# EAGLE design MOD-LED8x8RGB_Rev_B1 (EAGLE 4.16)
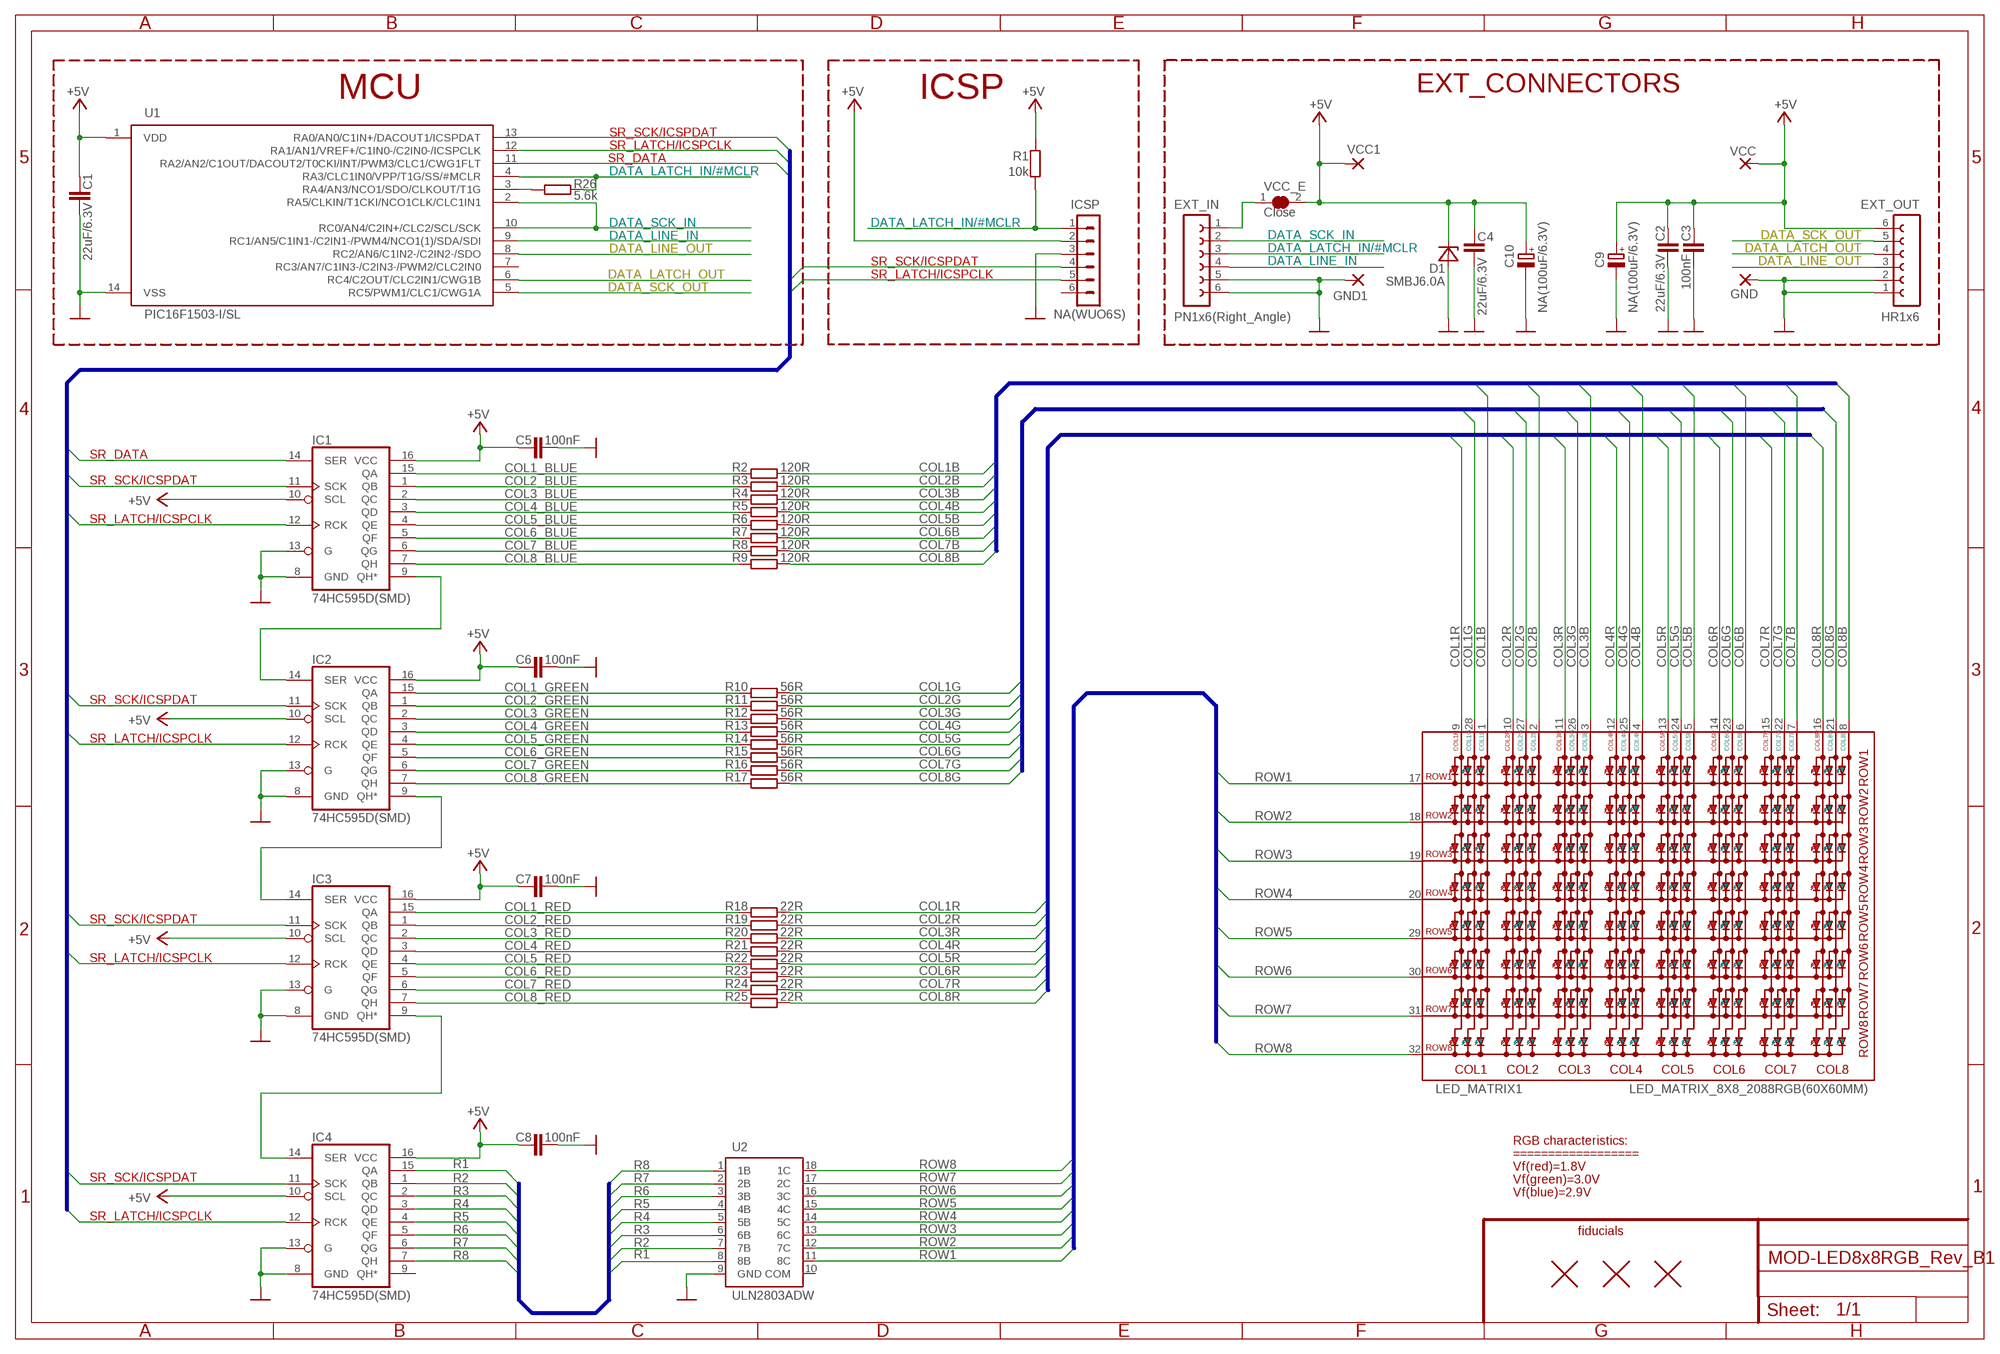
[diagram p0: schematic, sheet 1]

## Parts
C1  22uF/6.3V  C-EUC0603_DWS  [C0603_DWS]
C2  22uF/6.3V  C-EUC0603_DWS  [C0603_DWS]
C3  100nF  C-EUC0603_DWS  [C0603_DWS]
C4  22uF/6.3V  C-EUC0603_DWS  [C0603_DWS]
C5  100nF  C-EUC0603_DWS  [C0603_DWS]
C6  100nF  C-EUC0603_DWS  [C0603_DWS]
C7  100nF  C-EUC0603_DWS  [C0603_DWS]
C8  100nF  C-EUC0603_DWS  [C0603_DWS]
C9  NA(100uF/6.3V)  CPOL-EUC-SMD5X11-M  [C-SMD5X11-M]
C10  NA(100uF/6.3V)  CPOL-EUC-SMD5X11  [C-SMD5X11]
D1  SMBJ6.0A  SMBJ16A  [DO214AA]
EXT_IN  PN1x6(Right_Angle)  FE06W  [FE06W]
EXT_OUT  HR1x6  FE06W  [FE06W]
FID1  FIDUCIAL1X2  [FIDUCIAL-1X2]
FID2  FIDUCIAL1X2  [FIDUCIAL-1X2]
FID3  FIDUCIAL1X2  [FIDUCIAL-1X2]
GND  3,17/1,3  [3,17/1,3]
GND1  3,17/1,3  [3,17/1,3]
IC1  74HC595D(SMD)  74LS595D  [SO16]
IC2  74HC595D(SMD)  74LS595D  [SO16]
IC3  74HC595D(SMD)  74LS595D  [SO16]
IC4  74HC595D(SMD)  74LS595D  [SO16]
ICSP  NA(WUO6S)  CON6WUO6S  [WU06S]
LED_MATRIX1  LED_MATRIX_8X8_2088RGB(60X60MM)  [LED_MATRIX_8X8RGB_60X60MM]
R1  10k  R-EU_R0603_5MIL_DWS  [R0603_5MIL_DWS]
R2  120R  R-EU_R1206_5MIL_WS  [R1206_5MIL_WS]
R3  120R  R-EU_R1206_5MIL_WS  [R1206_5MIL_WS]
R4  120R  R-EU_R1206_5MIL_WS  [R1206_5MIL_WS]
R5  120R  R-EU_R1206_5MIL_WS  [R1206_5MIL_WS]
R6  120R  R-EU_R1206_5MIL_WS  [R1206_5MIL_WS]
R7  120R  R-EU_R1206_5MIL_WS  [R1206_5MIL_WS]
R8  120R  R-EU_R1206_5MIL_WS  [R1206_5MIL_WS]
R9  120R  R-EU_R1206_5MIL_WS  [R1206_5MIL_WS]
R10  56R  R-EU_R1206_5MIL_WS  [R1206_5MIL_WS]
R11  56R  R-EU_R1206_5MIL_WS  [R1206_5MIL_WS]
R12  56R  R-EU_R1206_5MIL_WS  [R1206_5MIL_WS]
R13  56R  R-EU_R1206_5MIL_WS  [R1206_5MIL_WS]
R14  56R  R-EU_R1206_5MIL_WS  [R1206_5MIL_WS]
R15  56R  R-EU_R1206_5MIL_WS  [R1206_5MIL_WS]
R16  56R  R-EU_R1206_5MIL_WS  [R1206_5MIL_WS]
R17  56R  R-EU_R1206_5MIL_WS  [R1206_5MIL_WS]
R18  22R  R-EU_R1206_5MIL_WS  [R1206_5MIL_WS]
R19  22R  R-EU_R1206_5MIL_WS  [R1206_5MIL_WS]
R20  22R  R-EU_R1206_5MIL_WS  [R1206_5MIL_WS]
R21  22R  R-EU_R1206_5MIL_WS  [R1206_5MIL_WS]
R22  22R  R-EU_R1206_5MIL_WS  [R1206_5MIL_WS]
R23  22R  R-EU_R1206_5MIL_WS  [R1206_5MIL_WS]
R24  22R  R-EU_R1206_5MIL_WS  [R1206_5MIL_WS]
R25  22R  R-EU_R1206_5MIL_WS  [R1206_5MIL_WS]
R26  5.6k  R-EU_R0603_5MIL_DWS  [R0603_5MIL_DWS]
U1  PIC16F1503-I/SL  PIC16F1503  [SOIC14]
U2  ULN2803ADW  [SO18-150MILS/2]
VCC  3,17/1,3  [3,17/1,3]
VCC1  3,17/1,3  [3,17/1,3]
VCC_E  Close  SJSJ-CLOSE  [SJ-CLOSE]

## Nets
+5V: C1.1 C2.1 C3.1 C4.1 C5.1 C6.1 C7.1 C8.1 C9.+ C10.+ D1.C EXT_OUT.6 IC1.10(SCL) IC1.16(VCC) IC2.10(SCL) IC2.16(VCC) IC3.10(SCL) IC3.16(VCC) IC4.10(SCL) IC4.16(VCC) ICSP.2 R1.1 U1.1(VDD) VCC1.1(P) VCC.1(P) VCC_E.2
COL1_BLUE: IC1.15(QA) R2.1
COL1_GREEN: IC2.15(QA) R10.1
COL1_RED: IC3.15(QA) R18.1
COL1B: LED_MATRIX1.1(COL1B) R2.2
COL1G: LED_MATRIX1.28(COL1G) R10.2
COL1R: LED_MATRIX1.9(COL1R) R18.2
COL2_BLUE: IC1.1(QB) R3.1
COL2_GREEN: IC2.1(QB) R11.1
COL2_RED: IC3.1(QB) R19.1
COL2B: LED_MATRIX1.2(COL2B) R3.2
COL2G: LED_MATRIX1.27(COL2G) R11.2
COL2R: LED_MATRIX1.10(COL2R) R19.2
COL3_BLUE: IC1.2(QC) R4.1
COL3_GREEN: IC2.2(QC) R12.1
COL3_RED: IC3.2(QC) R20.1
COL3B: LED_MATRIX1.3(COL3B) R4.2
COL3G: LED_MATRIX1.26(COL3G) R12.2
COL3R: LED_MATRIX1.11(COL3R) R20.2
COL4_BLUE: IC1.3(QD) R5.1
COL4_GREEN: IC2.3(QD) R13.1
COL4_RED: IC3.3(QD) R21.1
COL4B: LED_MATRIX1.4(COL4B) R5.2
COL4G: LED_MATRIX1.25(COL4G) R13.2
COL4R: LED_MATRIX1.12(COL4R) R21.2
COL5_BLUE: IC1.4(QE) R6.1
COL5_GREEN: IC2.4(QE) R14.1
COL5_RED: IC3.4(QE) R22.1
COL5B: LED_MATRIX1.5(COL5B) R6.2
COL5G: LED_MATRIX1.24(COL5G) R14.2
COL5R: LED_MATRIX1.13(COL5R) R22.2
COL6_BLUE: IC1.5(QF) R7.1
COL6_GREEN: IC2.5(QF) R15.1
COL6_RED: IC3.5(QF) R23.1
COL6B: LED_MATRIX1.6(COL6B) R7.2
COL6G: LED_MATRIX1.23(COL6G) R15.2
COL6R: LED_MATRIX1.14(COL6R) R23.2
COL7_BLUE: IC1.6(QG) R8.1
COL7_GREEN: IC2.6(QG) R16.1
COL7_RED: IC3.6(QG) R24.1
COL7B: LED_MATRIX1.7(COL7B) R8.2
COL7G: LED_MATRIX1.22(COL7G) R16.2
COL7R: LED_MATRIX1.15(COL7R) R24.2
COL8_BLUE: IC1.7(QH) R9.1
COL8_GREEN: IC2.7(QH) R17.1
COL8_RED: IC3.7(QH) R25.1
COL8B: LED_MATRIX1.8(COL8B) R9.2
COL8G: LED_MATRIX1.21(COL8G) R17.2
COL8R: LED_MATRIX1.16(COL8R) R25.2
DATA_LATCH_IN/#MCLR: EXT_IN.3 ICSP.1 R1.2 R26.2 U1.4(RA3/CLC1IN0/VPP/T1G/SS/#MCLR)
DATA_LATCH_OUT: EXT_OUT.4 U1.6(RC4/C2OUT/CLC2IN1/CWG1B)
DATA_LINE_IN: EXT_IN.4 U1.9(RC1/AN5/C1IN1-/C2IN1-/PWM4/NCO1(1)/SDA/SDI)
DATA_LINE_OUT: EXT_OUT.3 U1.8(RC2/AN6/C1IN2-/C2IN2-/SDO)
DATA_SCK_IN: EXT_IN.2 U1.2(RA5/CLKIN/T1CKI/NCO1CLK/CLC1IN1) U1.10(RC0/AN4/C2IN+/CLC2/SCL/SCK)
DATA_SCK_OUT: EXT_OUT.5 U1.5(RC5/PWM1/CLC1/CWG1A)
GND: C1.2 C2.2 C3.2 C4.2 C5.2 C6.2 C7.2 C8.2 C9.- C10.- D1.A EXT_IN.5 EXT_IN.6 EXT_OUT.1 EXT_OUT.2 GND1.1(P) GND.1(P) IC1.8(GND) IC1.13(G) IC2.8(GND) IC2.13(G) IC3.8(GND) IC3.13(G) IC4.8(GND) IC4.13(G) ICSP.3 U1.14(VSS) U2.9(GND)
N$1: R26.1 U1.3(RA4/AN3/NCO1/SDO/CLKOUT/T1G)
N$15: EXT_IN.1 VCC_E.1
N$29: IC3.9(QH*) IC4.14(SER)
N$45: IC1.9(QH*) IC2.14(SER)
N$46: IC2.9(QH*) IC3.14(SER)
R1: IC4.15(QA) U2.8(8B)
R2: IC4.1(QB) U2.7(7B)
R3: IC4.2(QC) U2.6(6B)
R4: IC4.3(QD) U2.5(5B)
R5: IC4.4(QE) U2.4(4B)
R6: IC4.5(QF) U2.3(3B)
R7: IC4.6(QG) U2.2(2B)
R8: IC4.7(QH) U2.1(1B)
ROW1: LED_MATRIX1.17(ROW1) U2.11(8C)
ROW2: LED_MATRIX1.18(ROW2) U2.12(7C)
ROW3: LED_MATRIX1.19(ROW3) U2.13(6C)
ROW4: LED_MATRIX1.20(ROW4) U2.14(5C)
ROW5: LED_MATRIX1.29(ROW5) U2.15(4C)
ROW6: LED_MATRIX1.30(ROW6) U2.16(3C)
ROW7: LED_MATRIX1.31(ROW7) U2.17(2C)
ROW8: LED_MATRIX1.32(ROW8) U2.18(1C)
SR_DATA: IC1.14(SER) U1.11(RA2/AN2/C1OUT/DACOUT2/T0CKI/INT/PWM3/CLC1/CWG1FLT)
SR_LATCH/ICSPCLK: IC1.12(RCK) IC2.12(RCK) IC3.12(RCK) IC4.12(RCK) ICSP.5 U1.12(RA1/AN1/VREF+/C1IN0-/C2IN0-/ICSPCLK)
SR_SCK/ICSPDAT: IC1.11(SCK) IC2.11(SCK) IC3.11(SCK) IC4.11(SCK) ICSP.4 U1.13(RA0/AN0/C1IN+/DACOUT1/ICSPDAT)
Unconnected: IC4.9(QH*) ICSP.6 U1.7(RC3/AN7/C1IN3-/C2IN3-/PWM2/CLC2IN0) U2.10(COM)

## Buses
SR_SCK,SR_LATCH,SR_DATA
COL1B,COL2B,COL3B,COL4B,COL5B,COL6B,COL7B,COL8B
COL1G,COL2G,COL3G,COL4G,COL5G,COL6G,COL7G,COL8G
COL1R,COL2R,COL3R,COL4R,COL5R,COL6R,COL7R,COL8R
R[1..8]
ROW[1..8]

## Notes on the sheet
- MCU | ICSP | EXT_CONNECTORS
- RGB characteristics:
- ==================
- Vf(red)=1.8V
- Vf(green)=3.0V
- Vf(blue)=2.9V
- fiducials

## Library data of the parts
C1-C8 = rcl:C-EU: CAPACITOR, European symbol
C9 C10 = rcl:CPOL-EU: POLARIZED CAPACITOR, European symbol
D1 = OLIMEX_DISCRET:SMBJ16A
EXT_IN EXT_OUT = con-lsta:FE06W: FEMALE HEADER
FID1-FID3 = SparkFunEagle-6-6-07:FIDUCIAL: Fiducial Alignment Points
GND GND1 VCC VCC1 = wirepad:3,17/1,3: THROUGH-HOLE PAD
IC1-IC4 = SparkFun:74*595: 8-bit SHIFT REGISTER, output latch
ICSP = Penko:CON6: CONNECTORS - 6 PINS
LED_MATRIX1 = OLIMEX_DISCRET:LED_MATRIX_8X8_2088RGB
R1-R26 = rcl:R-EU_: RESISTOR, European symbol
U1 = OLIMEX_IC:PIC16F1503
U2 = OLIMEX_IC:ULN2803
VCC_E = jumper:SJ: SMD solder JUMPER

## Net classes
1 pwr: width 1.016 mm, drill 0.241 mm

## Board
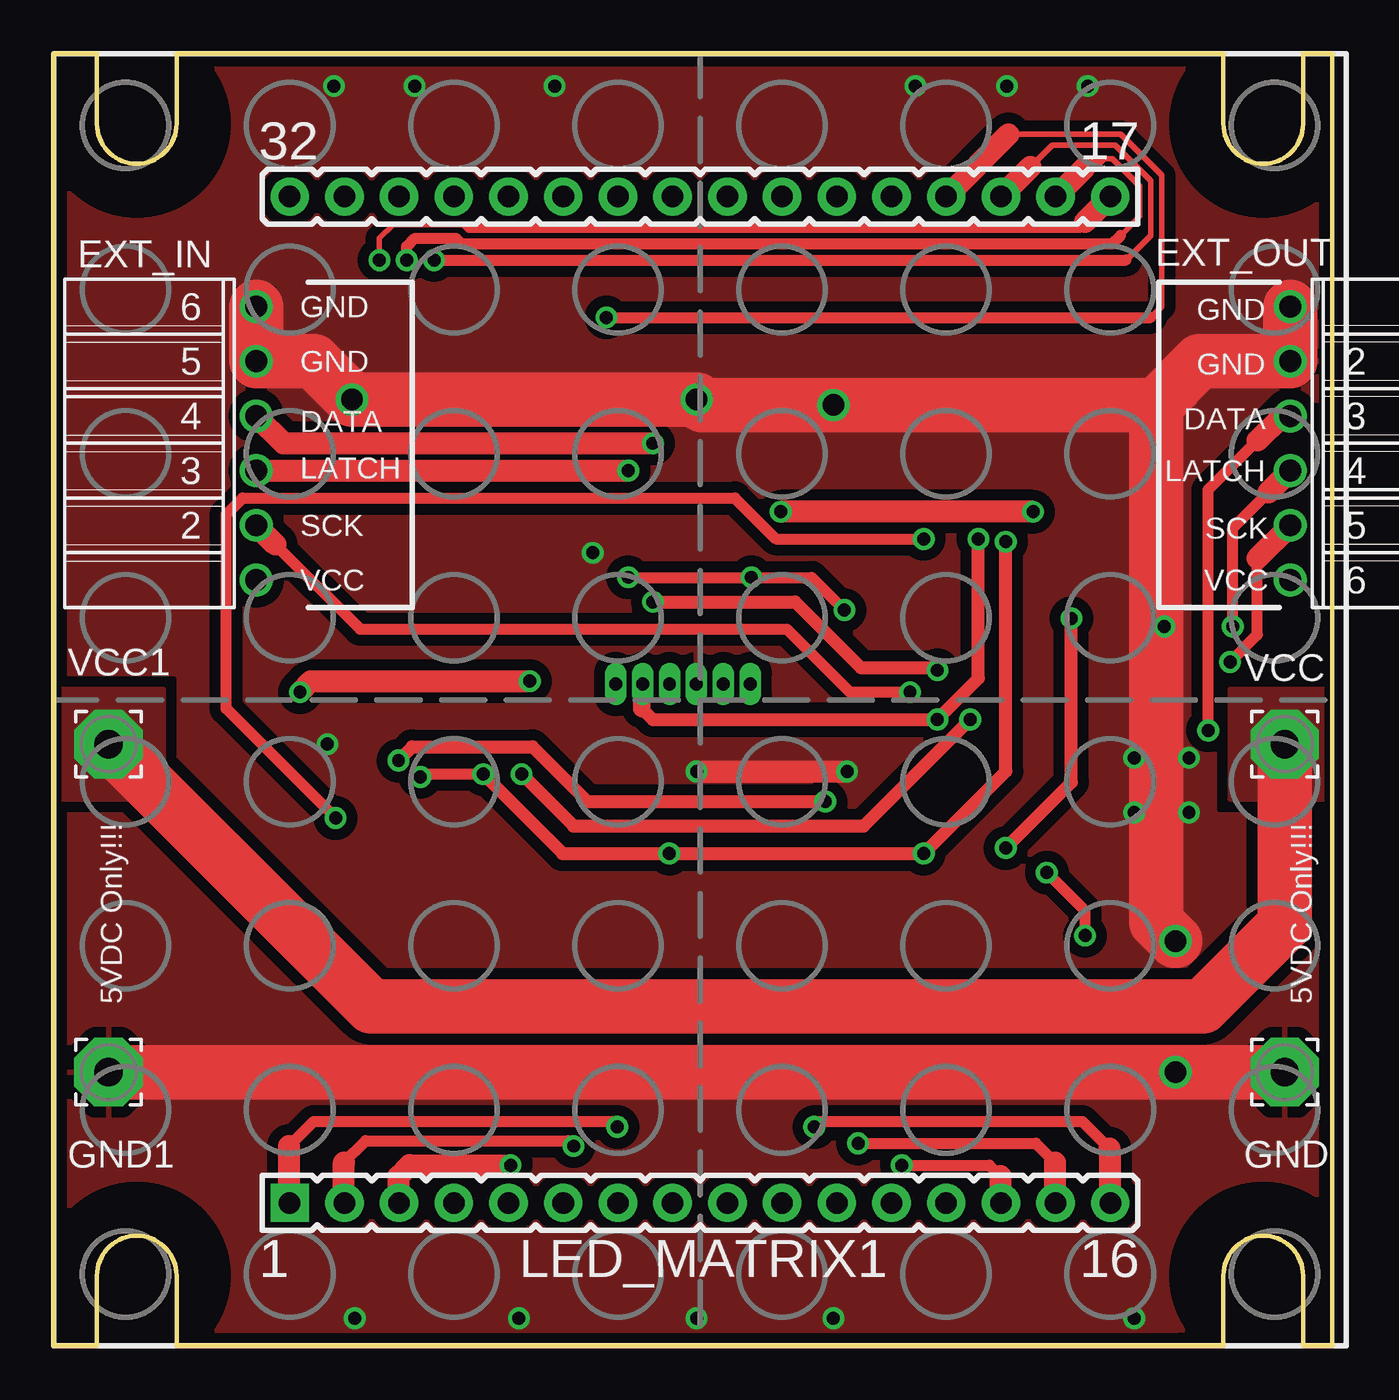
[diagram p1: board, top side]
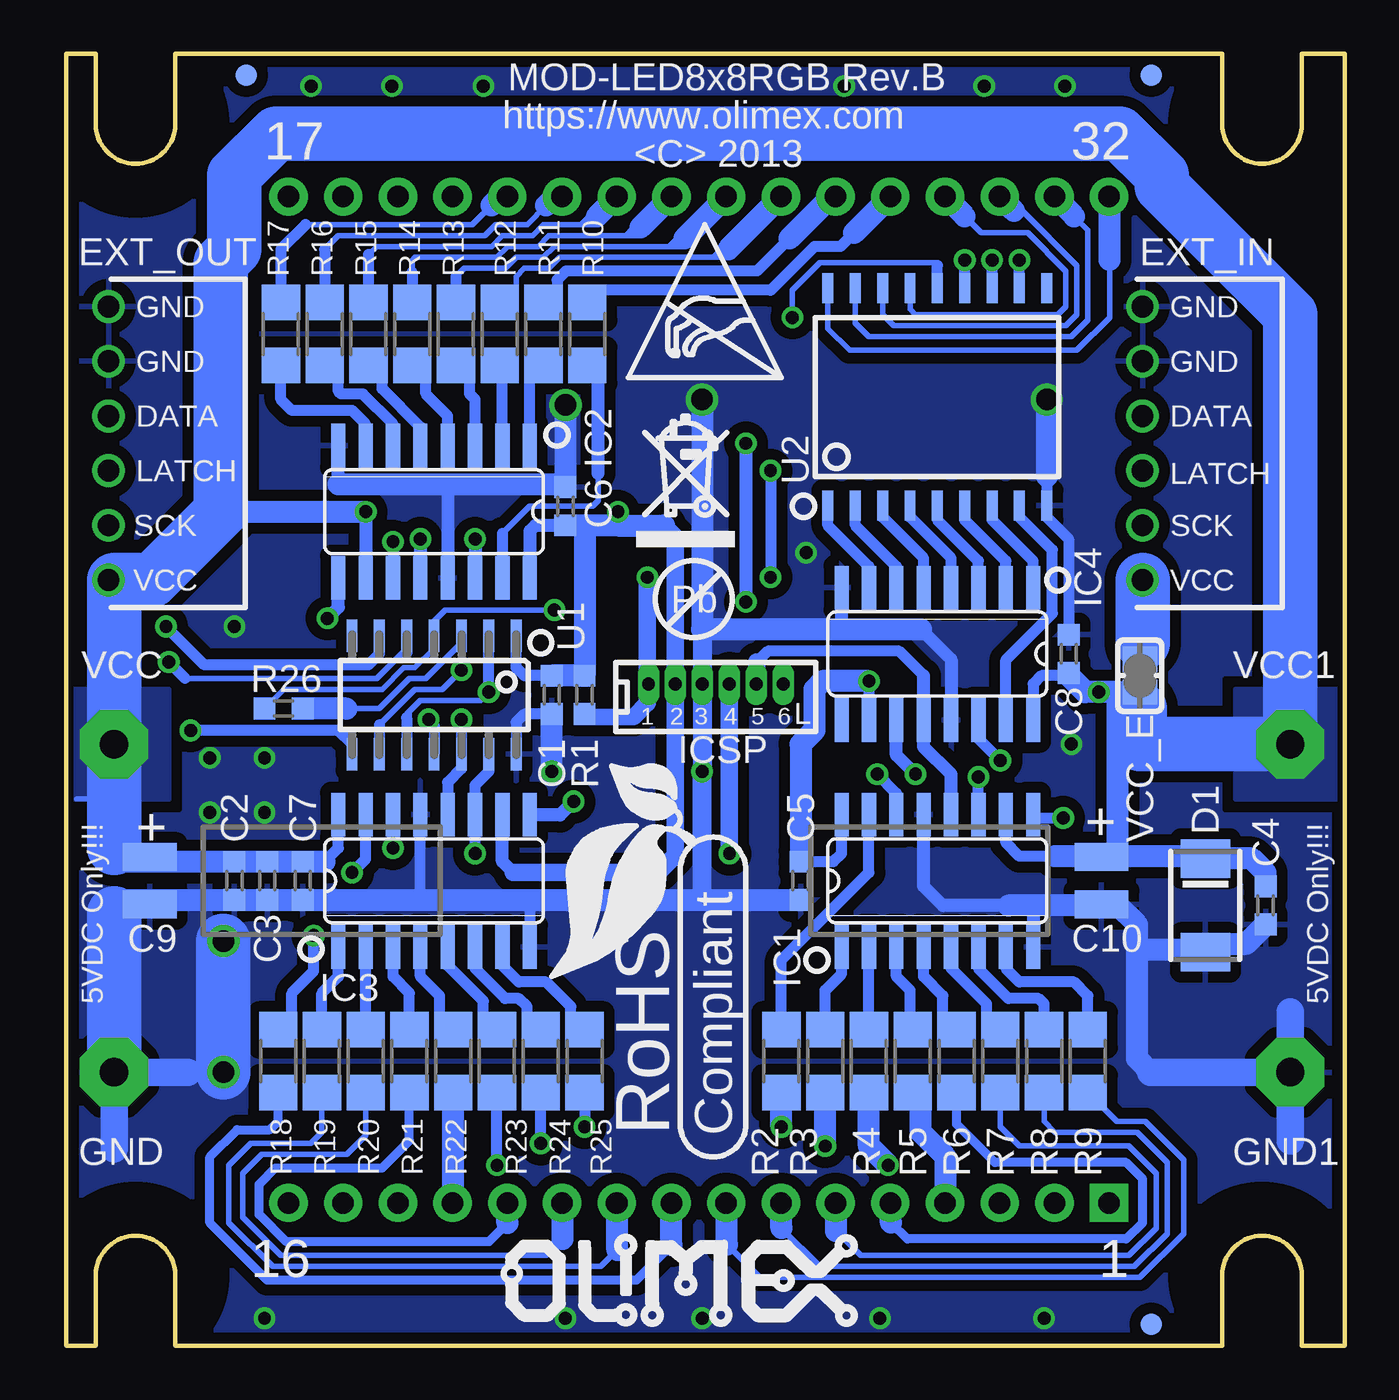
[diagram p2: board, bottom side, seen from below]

Size 59.37 x 60 mm. Coordinates in mm from the lower left corner, seen from the top.
Outline: 54.3,0 5.7,0 5.7,3.25 arc90 3.85,5.1 arc90 2,3.25 2,0 0,0 0,60 2,60 2,56.75 arc90 3.85,54.9 arc90 5.7,56.75 5.7,60 54.3,60 54.3,56.75 arc90 56.15,54.9 arc90 58,56.75 58,60 59.37,60 59.37,0 58,0 58,3.25 arc90 56.15,5.1 arc90 54.3,3.25 54.3,0
Outline: 52.3,0 54.3,0
Copper layers (1+16): Top 0.035mm / dielectric 1.5mm / Bottom 0.035mm
Design rules "default": minimum track width 10mil, minimum drill 23mil, track to track 10mil, track to pad 10mil, pad to pad 10mil, via to via 10mil, smd to smd 1mil, copper to edge 10mil, drill to drill 8mil, minimum pad ring 7mil, minimum via ring 8mil, stop-mask expansion 4mil, vias tented up to drill 40mil, thermal gap 20mil
tRestrict: area 0.1,-0.5 to 7.6,7; area 52.4,-0.5 to 59.9,7; area 52.4,53 to 59.9,60.5; area 0.1,53 to 7.6,60.5
bRestrict: area 0.1,-0.5 to 7.6,7; area 52.4,-0.5 to 59.9,7; area 52.4,53 to 59.9,60.5; area 0.1,53 to 7.6,60.5

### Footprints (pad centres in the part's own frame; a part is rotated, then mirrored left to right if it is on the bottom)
C0603_DWS = smd 1.016 x 1.016: 1 -0.889,0; 2 0.889,0
C-SMD5X11-M = smd 2.5 x 1.3: + 0,-1.1; - 0,1.1
C-SMD5X11 = smd 2.5 x 1.3: + 0,1.1; - 0,-1.1
DO214AA = smd 1.778 x 2.286: A 2.177,0; C -2.177,0
FE06W = drill 1.016 round: 1 -6.35,0; 2 -3.81,0; 3 -1.27,0; 4 1.27,0; 5 3.81,0; 6 6.35,0
FIDUCIAL-1X2 = smd 1 x 1: 1 0,0
3,17/1,3 = drill 1.321 pad 3.175 octagon: 1 0,0
SO16 = smd 0.66 x 2.032: 1 -4.445,-3.073; 2 -3.175,-3.073; 3 -1.905,-3.073; 4 -0.635,-3.073; 5 0.635,-3.073; 6 1.905,-3.073; 7 3.175,-3.073; 8 4.445,-3.073; 9 4.445,3.073; 10 3.175,3.073; 11 1.905,3.073; 12 0.635,3.073; 13 -0.635,3.073; 14 -1.905,3.073; 15 -3.175,3.073; 16 -4.445,3.073
WU06S = drill 0.6 pad 0.991 long: 1 -3.125,0; 2 -1.875,0; 3 -0.625,0; 4 0.625,0; 5 1.875,0; 6 3.125,0
LED_MATRIX_8X8RGB_60X60MM = drill 1 pad 1.778 square: 1 -19.05,-23.368 | drill 1 pad 1.778 round: 2 -16.51,-23.368; 3 -13.97,-23.368; 4 -11.43,-23.368; 5 -8.89,-23.368; 6 -6.35,-23.368; 7 -3.81,-23.368; 8 -1.27,-23.368; 9 1.27,-23.368; 10 3.81,-23.368; 11 6.35,-23.368; 12 8.89,-23.368; 13 11.43,-23.368; 14 13.97,-23.368; 15 16.51,-23.368; 16 19.05,-23.368; 17 19.05,23.368; 18 16.51,23.368; 19 13.97,23.368; 20 11.43,23.368; 21 8.89,23.368; 22 6.35,23.368; 23 3.81,23.368; 24 1.27,23.368; 25 -1.27,23.368; 26 -3.81,23.368; 27 -6.35,23.368; 28 -8.89,23.368; 29 -11.43,23.368; 30 -13.97,23.368; 31 -16.51,23.368; 32 -19.05,23.368
R0603_5MIL_DWS = smd 1.016 x 1.016: 1 -0.889,0; 2 0.889,0
R1206_5MIL_WS = smd 1.651 x 1.778: 1 -1.46,0; 2 1.46,0
SOIC14 = smd 0.5 x 1.5: 1 -3.81,-2.75; 2 -2.54,-2.75; 3 -1.27,-2.75; 4 0,-2.75; 5 1.27,-2.75; 6 2.54,-2.75; 7 3.81,-2.75; 8 3.81,2.75; 9 2.54,2.75; 10 1.27,2.75; 11 0,2.75; 12 -1.27,2.75; 13 -2.54,2.75; 14 -3.81,2.75
SO18-150MILS/2 = smd 0.508 x 1.397: 1 -5.08,-5.042; 2 -3.81,-5.042; 3 -2.54,-5.042; 4 -1.27,-5.042; 5 0,-5.042; 6 1.27,-5.042; 7 2.54,-5.042; 8 3.81,-5.042; 9 5.08,-5.042; 10 5.08,5.042; 11 3.81,5.042; 12 2.54,5.042; 13 1.27,5.042; 14 0,5.042; 15 -1.27,5.042; 16 -2.54,5.042; 17 -3.81,5.042; 18 -5.08,5.042
SJ-CLOSE = smd 1.168 x 1.6: 1 -0.762,0; 2 0.762,0

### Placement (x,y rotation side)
C1  36.83,30.23 270 bottom
C2  51.56,21.59 270 bottom
C3  50.04,21.59 270 bottom
C4  3.68,20.45 270 bottom
C5  25.27,21.59 270 bottom
C6  36.2,38.99 90 bottom
C7  48.39,21.59 270 bottom
C8  12.83,32.13 90 bottom
C9  55.5,21.59 180 bottom
C10  11.3,21.59 0 bottom
D1  6.48,20.45 270 bottom
EXT_IN  9.4,41.91 90 top
EXT_OUT  57.4,41.91 270 top
FID1  9,1 0 bottom
FID2  51,59 0 bottom
FID3  9,59 0 bottom
GND  57.15,12.7 0 top
GND1  2.54,12.7 0 top
IC1  18.92,21.59 0 bottom
IC2  42.29,38.73 180 bottom
IC3  42.29,21.59 0 bottom
IC4  18.92,32.13 180 bottom
ICSP  29.21,30.73 0 bottom
LED_MATRIX1  30,30 0 top
R1  35.31,30.23 270 bottom
R2  26.16,13.21 270 bottom
R3  24.13,13.21 270 bottom
R4  22.1,13.21 270 bottom
R5  20.07,13.21 270 bottom
R6  18.03,13.21 270 bottom
R7  16,13.21 270 bottom
R8  13.97,13.21 270 bottom
R9  11.94,13.21 270 bottom
R10  35.18,46.99 90 bottom
R11  37.21,46.99 90 bottom
R12  39.24,46.99 90 bottom
R13  41.27,46.99 90 bottom
R14  43.31,46.99 90 bottom
R15  45.34,46.99 90 bottom
R16  47.37,46.99 90 bottom
R17  49.4,46.99 90 bottom
R18  49.53,13.21 270 bottom
R19  47.5,13.21 270 bottom
R20  45.47,13.21 270 bottom
R21  43.43,13.21 270 bottom
R22  41.4,13.21 270 bottom
R23  39.37,13.21 270 bottom
R24  37.34,13.21 270 bottom
R25  35.31,13.21 270 bottom
R26  49.28,29.59 180 bottom
U1  42.29,30.23 180 bottom
U2  18.92,44.07 0 bottom
U$1  [ESD_SYMBOL]  33.27,44.96 0 bottom
U$2  [ROHS]  28.45,9.78 90 bottom
U$5  [PB_SMALL]  30.23,34.67 0 bottom
U$6  [RECYCLE_BIN1/8]  32.89,37.08 0 bottom
U$7  [OLIMEX1_V]  21.46,0.76 0 bottom
VCC  57.15,27.94 0 top
VCC1  2.54,27.94 0 top
VCC_E  9.53,31.11 270 bottom

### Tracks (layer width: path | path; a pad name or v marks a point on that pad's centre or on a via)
+5V  (via drill 0.6)
  Top 1.016: v45.47,38.73 v33.75,38.73 | v11.43,30.35 11.94,30.86 v22.1,30.86
  Top 2.54: VCC.1 57.15,19.56 53.34,15.75 14.73,15.75 VCC1.1
  Bottom 0.254: 37.85,35.81 IC2.16 37.85,35.94 | 58.88,25.4 58.42,25.4
  Bottom 0.508: U1.1 38.48,31.5 38.1,31.11 C1.1 | 12.83,31.11 14.1,31.11 14.48,30.73 IC4.16 | IC1.10 15.75,23.37 15.11,22.73 13.46,22.73 | v22.1,30.86 IC4.10 | C5.1 23.75,22.48 23.37,22.86 IC1.16 | IC3.16 46.74,23.11 47.37,22.48
  Bottom 0.61: C6.1 37.59,38.1 37.85,37.85 37.85,35.94 | VCC.1 57.15,27.81 | v45.47,38.73 IC2.10 | 38.61,21.97 39.12,22.48 IC3.10
  Bottom 0.813: 31.62,38.1 31.09,37.56 ICSP.2 31.09,22.76 31.88,21.97 38.61,21.97
  Bottom 1.016: C8.1 12.83,31.11 12.06,30.35 v11.43,30.35 10.54,30.35 | 9.53,29.59 VCC_E.2 10.54,30.35 | C4.1 3.68,21.97 4.34,22.62 D1.C 6.59,22.73 10.54,22.73 | 57.15,23.11 56.52,22.48 55.5,22.48 | 55.5,22.48 C2.1 C3.1 C7.1 47.37,22.48 | 35.31,38.1 C6.1 | 52.2,38.73 v45.47,38.73 | 35.31,38.1 R1.1 C1.1 | v33.75,38.73 33.75,38.1 | 33.75,38.1 31.62,38.1 | C5.1 25.27,27.94 24.64,28.57 24.64,30.48 24.26,30.86 v22.1,30.86 | 33.75,38.1 35.31,38.1 | 57.15,35.56 EXT_OUT.6 | 10.54,22.73 11.26,22.73 | 55.5,22.48 C9.+ | 11.26,22.73 C10.+ 11.35,22.73 11.43,22.73 | 11.26,22.73 11.3,22.73 | 11.43,22.73 13.46,22.73 | 10.54,22.73 11.43,22.73 | 10.54,22.73 10.54,30.35
  Bottom 2.54: 9.53,29.59 9.53,27.94 VCC1.1 2.54,47.88 8.51,53.85 8.51,54.36 10.45,56.29 49.62,56.29 51.56,54.36 51.56,50.93 52.2,50.29 52.2,38.73 55.37,35.56 57.15,35.56 VCC.1 57.15,23.11
  pour Top (isolate 0.025, no thermals): 54.61,30.48 59.69,30.48 59.69,25.4 54.61,25.4
  pour Top (isolate 0.254, no thermals): 0,30.48 5.08,30.48 5.08,25.4 0,25.4
  pour Bottom (isolate 0.025, no thermals): 54.61,30.48 59.69,30.48 59.69,25.4 54.61,25.4
  pour Bottom (isolate 0.254, no thermals): 0,30.48 5.08,30.48 5.08,25.4 0,25.4
COL1_BLUE
  Bottom 0.508: R2.1 26.16,17.91 22.1,21.97 IC1.15
COL1_GREEN
  Bottom 0.254: 34.67,40.51 34.67,39.24 34.92,38.99 37.85,38.99 39.12,37.72
  Bottom 0.508: 39.12,37.72 IC2.15
  Bottom 0.61: R10.1 34.67,45.02 34.67,40.51
COL1_RED  (via drill 0.6)
  Top 0.508: v47.88,19.05 47.88,20.19 v46.1,21.97
  Bottom 0.508: v47.88,19.05 47.88,17.4 48.9,16.38 48.9,15.3 R18.1 | IC3.15 45.47,22.61 v46.1,21.97
COL1B  (via drill 0.6)
  Top 0.508: 10.92,9.27 12.06,10.41 25.91,10.41 v26.16,10.16
  Top 1.016: LED_MATRIX1.1 10.92,6.6 10.92,9.27
  Bottom 1.016: v26.16,10.16 R2.2
COL1G
  Bottom 0.508: R10.2 35.18,49.02 26.67,49.02 24.64,51.05 23.42,51.05 22.79,51.69
  Bottom 1.016: 22.79,51.69 LED_MATRIX1.28
COL1R
  Bottom 0.406: R18.2 49.53,10.41 49.91,10.03 51.44,10.03 52.7,8.76 52.7,5.71 50.04,3.05 32.89,3.05 31.27,4.67
  Bottom 1.016: 31.27,4.67 LED_MATRIX1.9
COL2_BLUE
  Bottom 0.254: IC1.1 23.37,18.54
  Bottom 0.508: R3.1 24.13,16.51 23.37,17.27 IC1.1
COL2_GREEN
  Bottom 0.508: R11.1 37.21,45.47 37.85,44.83 IC2.1
COL2_RED
  Bottom 0.508: R19.1 47.5,16.38 46.74,17.14 IC3.1
COL2B  (via drill 0.6)
  Top 0.508: 13.46,8.51 14.48,9.53 23.88,9.53 v24.13,9.27
  Top 1.016: LED_MATRIX1.2 13.46,6.63 13.46,8.51
  Bottom 1.016: v24.13,9.27 R3.2
COL2G
  Bottom 0.508: R11.2 36.58,48.45 36.58,49.51 36.17,49.91 27.3,49.91 25.78,51.44
  Bottom 1.016: 25.78,51.44 23.85,53.37 LED_MATRIX1.27
COL2R
  Bottom 0.254: R19.2 47.5,9.91 48.01,9.4 50.8,9.4 51.82,8.38 51.82,5.71 49.78,3.68 34.54,3.68 33.78,4.45
  Bottom 1.016: 33.78,4.45 33.78,6.63 LED_MATRIX1.10
COL3_BLUE
  Bottom 0.508: R4.1 IC1.2
COL3_GREEN
  Bottom 0.254: R12.1 39.24,45.47
  Bottom 0.508: IC2.2 39.12,45.09 39.24,45.21 R12.1 39.24,45.59
COL3_RED
  Bottom 0.254: IC3.2 45.47,18.54
  Bottom 0.508: R20.1 IC3.2
COL3B  (via drill 0.6)
  Top 1.016: LED_MATRIX1.3 16,6.63 16,7.87 16.51,8.38 v21.21,8.38
  Bottom 1.016: v21.21,8.38 22.1,9.27 R4.2
COL3G
  Bottom 0.254: R12.2 39.24,48.51 38.48,48.51 38.48,49.66 38.1,50.04 36.96,50.04 36.45,50.55 29.34,50.55 | 29.34,50.55 28.63,50.55 28.63,50.93 | 29.34,50.55 28.83,51.05
  Bottom 1.016: 28.63,50.93 LED_MATRIX1.26
COL3R
  Bottom 0.254: R20.2 45.47,9.78 46.35,8.89 50.29,8.89 51.18,8 51.18,5.97 49.4,4.19 37.08,4.19 36.32,4.95
  Bottom 1.016: 36.32,4.95 36.32,6.6 LED_MATRIX1.11
COL4_BLUE
  Bottom 0.254: R5.1 20.19,14.67 | 20.83,17.4 IC1.3 20.83,18.54
  Bottom 0.508: 20.19,14.67 20.19,16.51 20.83,17.14 IC1.3
COL4_GREEN
  Bottom 0.508: IC2.3 40.39,43.94 40.64,44.2 40.64,45.53 R13.1
COL4_RED
  Bottom 0.508: R21.1 43.43,16.38 44.2,17.14 IC3.3
COL4B
  Bottom 0.254: 18.54,6.6 18.57,6.6 LED_MATRIX1.4
  Bottom 0.61: 19.68,11.68 19.68,11.75 R5.2
  Bottom 1.016: 18.54,6.6 18.54,8.76 19.68,9.91 19.68,11.68
COL4G
  Bottom 0.254: 41.27,49.66 40.89,50.04 38.99,50.04 38.48,50.55 37.21,50.55 36.7,51.05 31.37,51.05 | 30.66,51.44 30.66,51.05 31.37,51.05 | 31.37,51.05 30.99,51.44
  Bottom 0.508: 41.27,49.66 R13.2
  Bottom 1.016: LED_MATRIX1.25 30.66,51.44
COL4R
  Bottom 0.406: R21.2 43.43,9.53 44.7,8.26 49.66,8.26 50.42,7.49 50.42,6.1 49.15,4.83 39.75,4.83 38.89,5.69
  Bottom 1.016: 38.89,5.69 LED_MATRIX1.12
COL5_BLUE
  Bottom 0.508: IC1.4 19.56,17.14 18.67,16.26 18.67,14.67 R6.1
COL5_GREEN
  Bottom 0.508: IC2.4 41.66,43.18 42.67,44.2 42.67,45.53 R14.1
COL5_RED
  Bottom 0.508: R22.1 41.4,14.61 42.04,15.24 42.04,16.26 42.93,17.14 IC3.4 42.93,18.54
COL5B
  Bottom 0.406: R6.2 18.03,10.29 16.26,8.51 10.16,8.51 9.4,7.75 9.4,5.71 10.16,4.95 20.32,4.95 21.08,5.71
  Bottom 1.016: 21.08,5.71 21.08,6.63 LED_MATRIX1.5
COL5G
  Bottom 0.254: 33.4,51.56 32.7,51.56 32.7,51.94 | 33.4,51.56 36.96,51.56 37.47,51.05 38.86,51.05 39.37,50.55 43.18,50.55 43.31,50.42 43.31,49.85 | 33.4,51.56 33.02,51.94
  Bottom 0.508: 43.31,49.85 R14.2
  Bottom 1.016: 32.7,51.94 LED_MATRIX1.24
COL5R
  Bottom 1.016: LED_MATRIX1.13 41.4,6.63 R22.2
COL6_BLUE
  Bottom 0.508: R7.1 16.64,15.3 16.64,15.88 18.29,17.53 IC1.5
COL6_GREEN
  Bottom 0.508: 42.93,41.78 42.93,42.67 44.7,44.45 44.7,45.53 R15.1
  Bottom 0.61: IC2.5 42.93,41.78
COL6_RED
  Bottom 0.508: R23.1 40.01,14.67 40.01,16 41.66,17.65 IC3.5
COL6B
  Bottom 0.254: R7.2 16,10.16 15.11,9.27 10.03,9.27 8.76,8 8.76,5.46 10.03,4.19 22.48,4.19 23.62,5.33
  Bottom 1.016: 23.62,5.33 23.62,6.6 23.65,6.6 LED_MATRIX1.6
COL6G
  Bottom 0.254: 34.73,52.45 34.73,52.07 35.49,52.07 | 35.49,52.07 37.21,52.07 37.72,51.56 39.12,51.56 39.62,51.05 44.96,51.05 45.34,50.67 | 35.49,52.07 34.85,52.7
  Bottom 0.508: 45.34,50.67 R15.2
  Bottom 1.016: 34.73,52.45 LED_MATRIX1.23
COL6R  (via drill 0.6)
  Top 0.508: 43.94,7.87 43.43,8.38 v39.37,8.38
  Top 1.016: 43.94,7.87 43.94,6.63 | 43.94,6.63 43.94,6.6 | 43.94,6.63 LED_MATRIX1.14
  Bottom 0.508: v39.37,8.38 R23.2
COL7_BLUE
  Bottom 0.406: 17.02,18.54 IC1.6
  Bottom 0.508: R8.1 13.97,15.88 14.22,16.13 15.62,16.13 17.02,17.53 17.02,18.54 17.02,18.67
COL7_GREEN
  Bottom 0.508: 44.2,41.78 IC2.6 44.2,42.8 45.59,44.2 46.61,44.2 46.74,44.32 46.74,44.96 47.37,45.59 R16.1
COL7_RED
  Bottom 0.508: IC3.6 40.39,17.53 38.99,16.13 38.35,16.13 37.97,15.75 37.97,14.61 37.4,14.61 R24.1
COL7B
  Bottom 0.254: R8.2 13.97,10.41 13.46,9.91 9.65,9.91 8.26,8.51 8.26,5.21 9.78,3.68 24.38,3.68 26.16,5.46
  Bottom 1.016: LED_MATRIX1.7 26.16,6.63 26.16,5.46
COL7G
  Bottom 0.254: 47.37,50.93 46.74,51.56 39.93,51.56 39.43,52.07 37.97,52.07 37.08,52.96
  Bottom 0.508: 47.37,50.93 R16.2
  Bottom 1.016: LED_MATRIX1.22 36.67,53.37 37.08,52.96
COL7R  (via drill 0.6)
  Top 0.508: 46.48,8.51 45.59,9.4 v37.34,9.4
  Top 1.016: 46.48,8.51 46.48,6.6 LED_MATRIX1.15
  Bottom 0.508: v37.34,9.4 R24.2
COL8_BLUE
  Bottom 0.508: R9.1 11.94,16.26 12.57,16.89 15.11,16.89 15.75,17.53 IC1.7 15.75,18.54
COL8_GREEN
  Bottom 0.508: IC2.7 45.47,42.8 46.1,43.43 48.9,43.43 49.4,43.94 R17.1
COL8_RED
  Bottom 0.508: 35.31,14.61 R25.1 35.94,14.67 35.94,15.11 | 35.94,15.11 35.94,14.99 | 35.94,15.11 35.94,15.75 37.08,16.89 38.35,16.89 39.12,17.65 IC3.7 39.12,18.54
COL8B
  Bottom 0.254: R9.2 10.6,10.41 9.27,10.41 7.49,8.64 7.49,5.21 9.53,3.17 27.18,3.17 28.7,4.7
  Bottom 1.016: 28.7,4.7 28.7,6.73 28.73,6.7 LED_MATRIX1.8
COL8G
  Bottom 0.254: 39.62,52.96 40.51,52.07 48.26,52.07
  Bottom 0.508: R17.2 49.4,50.93 48.26,52.07
  Bottom 1.016: 39.62,52.96 39.22,53.37 LED_MATRIX1.21
COL8R  (via drill 0.6)
  Top 0.508: v35.31,10.16 35.56,10.41 47.75,10.41 49.02,9.14
  Top 1.016: LED_MATRIX1.16 49.02,6.66 49.02,9.14
  Bottom 0.508: R25.2 v35.31,10.16
DATA_LATCH_IN/#MCLR  (via drill 0.6)
  Top 0.508: v26.67,35.69 v32.38,35.69 35.18,35.69 v36.7,34.16
  Top 1.016: EXT_IN.3 v26.67,40.64
  Bottom 0.254: v36.7,34.16 41.78,34.16 42.29,33.66 U1.4 42.29,32.38 43.18,31.5 43.69,31.5 44.7,30.48 49.28,30.48 R26.2 | R1.2 35.56,29.34
  Bottom 0.508: v26.67,40.64 v26.67,35.69
  Bottom 0.762: 33.4,29.21 35.18,29.21 R1.2 | 33.4,29.21 33.27,29.21 | 32.38,29.84 33.02,29.21 33.4,29.21
  Bottom 0.813: v32.38,35.69 32.38,30.78 ICSP.1 32.38,30.68 32.38,29.84
DATA_LATCH_OUT  (via drill 0.6)
  Top 0.508: v54.74,33.4 54.74,37.97 56.39,39.62
  Top 1.016: 56.39,39.62 EXT_OUT.4
  Bottom 0.508: U1.6 44.83,32.13 45.34,31.62 52.96,31.62 v54.74,33.4
DATA_LINE_IN  (via drill 0.6)
  Top 0.61: v27.81,34.54 34.42,34.54 37.47,31.5 40.89,31.5 v41.02,31.37
  Top 1.016: EXT_IN.4 10.67,41.91 v27.81,41.91
  Bottom 0.254: v41.02,31.37 41.91,30.48 43.18,30.48 44.83,28.83
  Bottom 0.508: 44.83,28.83 U1.9
  Bottom 0.61: v27.81,41.91 v27.81,34.54
DATA_LINE_OUT  (via drill 0.6)
  Top 0.508: v53.59,28.57 53.59,39.75 55.88,42.04
  Top 1.016: 55.88,42.04 57.02,43.18 EXT_OUT.3
  Bottom 0.508: U1.8 46.1,27.94 46.74,28.57 v53.59,28.57
DATA_SCK_IN  (via drill 0.6)
  Top 0.508: v39.75,30.35 36.96,30.35 34.04,33.27 14.22,33.27 10.29,37.21
  Top 1.016: EXT_IN.2 10.29,37.21
  Bottom 0.254: v39.75,30.35 40.13,29.97 42.93,29.97 43.43,29.46 | 43.43,29.46 43.56,29.34 43.56,29.16 | 43.43,29.46 43.43,29.16
  Bottom 0.508: v39.75,30.35 U1.2 | 43.56,29.16 U1.10
DATA_SCK_OUT  (via drill 0.6)
  Top 0.508: v54.61,31.75 55.88,33.02 55.88,36.58
  Top 1.016: 55.88,36.58 EXT_OUT.5
  Bottom 0.254: 43.56,32.13 43.69,32 43.94,32 | 43.94,32 44.96,30.99 53.85,30.99 | 43.56,32.38 43.94,32
  Bottom 0.508: U1.5 43.56,32.38 43.56,32.13 | 53.85,30.99 v54.61,31.75
GND  (via drill 0.6, 1)
  Top 1.016: v29.84,26.67 v36.83,26.67
  Top 2.54: EXT_OUT.1 EXT_OUT.2 53.21,45.72 51.18,43.69 | EXT_IN.6 EXT_IN.5 12.06,45.72 v13.84,43.94 v29.84,43.94 30.1,43.69 v36.2,43.69 51.18,43.69 | GND1.1 v52.07,12.7 GND.1 | v52.07,18.8 51.18,19.68 51.18,43.69
  Bottom 0.254: IC2.8 46.74,42.04
  Bottom 0.406: U2.9 13.84,38.99 | IC1.8 14.48,18.41
  Bottom 0.508: C8.2 12.83,37.47 13.84,38.48 U2.9 13.84,40.39 | U1.14 38.48,28.96 38.1,29.34 C1.2 | 37.85,20.7 IC3.8 | 42.93,20.7 IC3.13
  Bottom 0.61: 19.68,33.27 18.29,31.88 IC4.13 | C3.2 49.91,20.7 | C3.2 C2.2 | C7.2 C3.2 | 46.74,40.01 IC2.8 | IC1.13 19.56,21.34 18.67,20.45 15.62,20.45 | 41.66,40.01 IC2.13 | 23.37,33.27 IC4.8 | 6.48,18.29 D1.A 6.48,18.41 | 14.48,20.45 IC1.8
  Bottom 0.813: ICSP.3
  Bottom 0.889: 29.84,20.7 v29.84,26.67 ICSP.3 29.84,33.27
  Bottom 1.016: 19.68,33.27 23.37,33.27 29.84,33.27 v29.84,43.94 | 55.5,20.7 C7.2 42.93,20.7 37.85,20.7 29.84,20.7 C5.2 | 55.5,20.7 56.52,20.7 57.15,20.07 | 46.74,40.01 41.66,40.01 36.2,40.01 C6.2 v36.2,43.69 | v13.84,43.94 13.84,40.39 | 9.02,12.7 9.65,13.34 9.65,18.41 | 9.65,18.41 9.65,19.56 10.54,20.45 11.3,20.45 | 11.3,20.45 14.48,20.45 15.62,20.45 | v36.83,26.67 C1.2 | 6.48,18.41 6.48,18.29 | 6.48,18.41 6.48,18.67 4.57,18.67 C4.2 | 9.65,18.41 6.48,18.41 | 55.5,20.7 C9.- | 11.3,20.45 C10.-
  Bottom 1.27: GND1.1 9.02,12.7 | GND1.1 2.54,15.49 | 2.54,9.53 GND1.1 | 53.72,12.7 GND.1 57.15,9.14
  Bottom 2.54: GND.1 57.15,20.07 | v52.07,12.7 v52.07,18.8
  other vias: 50.16,27.3 52.7,27.3 50.16,24.77 52.7,24.77 13,58.5 48,58.5 40,58.5 16.75,58.5 23.25,58.5 29.84,1.27 13.97,1.27 21.59,1.27 36.2,1.27 50.16,1.27 12.7,27.94 44.25,58.5 25.02,36.83 51.56,33.4
  pour Bottom (isolate 0.508, rank 2): 69.64,63.63 -20.37,63.63 -20.37,-3.94 69.64,-3.94
  pour Top (isolate 0.508, rank 2): -9.8,62.36 65,62.36 65,-2.16 -9.8,-2.16
N$1
  Bottom 0.254: U1.3 41.02,32.64 42.67,30.99 43.43,30.99 44.83,29.59 46.35,29.59
  Bottom 1.016: 46.35,29.59 R26.1
N$15
  Bottom 1.016: VCC_E.1 9.4,32 9.4,32.64
  Bottom 2.54: 9.4,32.64 EXT_IN.1
N$29  (via drill 0.6)
  Top 0.61: v16,27.18 16.64,27.81 22.23,27.81 24.77,25.27 v35.81,25.27
  Bottom 0.254: IC4.14 17.02,29.08
  Bottom 0.508: IC4.14 17.02,28.19 v16,27.18
  Bottom 0.61: IC3.9 37.82,24.64 36.45,24.64 v35.81,25.27
N$45  (via drill 0.6)
  Top 0.508: v40.39,37.47 33.53,37.47 31.62,39.37 8.76,39.37 8,38.61 8,29.59 v13.08,24.51
  Bottom 0.508: IC1.9 14.48,24.51 v13.08,24.51
  Bottom 0.61: v40.39,37.47 IC2.14
N$46  (via drill 0.6)
  Top 0.61: v44.2,23.11 47.24,26.16 v47.24,33.78
  Bottom 0.61: IC3.14 v44.2,23.11 | v47.24,33.78 46.74,34.29 IC2.9
R1
  Bottom 0.508: U2.8 15.11,38.48 13.59,36.96 13.59,34.01 15.75,31.85 IC4.15
R2
  Bottom 0.508: IC4.1 14.48,36.45 16.38,38.35 U2.7
R3
  Bottom 0.508: 15.75,35.18 IC4.2 15.75,36.45 17.65,38.35 U2.6
R4
  Bottom 0.508: IC4.3 17.02,36.45 18.92,38.35 U2.5
R5
  Bottom 0.508: IC4.4 18.29,36.58 20.19,38.48 U2.4
R6
  Bottom 0.508: IC4.5 19.56,36.58 21.46,38.48 U2.3
R7
  Bottom 0.508: IC4.6 20.83,36.2 22.73,38.1 U2.2
R8
  Bottom 0.508: IC4.7 22.1,36.2 24,38.1 U2.1
ROW1  (via drill 0.6)
  Top 0.254: 49.02,53.34 49.05,53.34 LED_MATRIX1.17 | v15.11,50.42 15.11,51.44 15.75,52.07 19,52.07 | 19,52.07 19.18,52.07 19.3,51.94 | 19,52.07 19.25,51.82
  Top 0.508: 19.3,51.94 47.62,51.94 47.88,52.2
  Top 1.016: 47.88,52.2 49.02,53.34
  Bottom 0.508: U2.11 v15.11,50.42
ROW2  (via drill 0.6)
  Top 0.254: 49.53,51.56 50.42,52.45 50.42,53.85 49.15,55.12 48.77,55.12 | 48.77,55.12 48.13,55.12 47.88,54.86 47.88,54.74 48.39,54.74 48.77,55.12 | 48.77,55.12 48.26,54.61 48.26,54.86 48.39,54.99
  Top 0.508: v16.38,50.42 16.38,51.05 16.76,51.44 18.67,51.44 18.92,51.18 49.15,51.18 49.53,51.56
  Top 1.016: 47.88,54.74 LED_MATRIX1.18
  Bottom 0.508: U2.12 v16.38,50.42
ROW3  (via drill 0.6)
  Top 0.254: 49.78,50.42 50.93,51.56 50.93,54.1 49.28,55.75 46.35,55.75 45.34,54.74
  Top 0.508: v17.65,50.42 49.78,50.42
  Top 1.016: 43.94,53.34 LED_MATRIX1.19 45.34,54.74
  Bottom 0.508: U2.13 v17.65,50.42
ROW4  (via drill 0.6)
  Top 0.254: 50.93,47.75 51.44,48.26 51.44,54.36 49.53,56.26 44.32,56.26
  Top 0.508: v25.65,47.75 50.93,47.75
  Top 1.016: 44.32,56.26 LED_MATRIX1.20
  Bottom 0.254: 18.92,50.16 19.05,50.29 24.38,50.29 25.65,49.02 v25.65,47.75
  Bottom 0.508: U2.14 18.92,50.16
ROW5
  Bottom 0.254: 20.19,49.66 U2.15 20.19,48.13 19.94,47.88 13.34,47.88 12.95,48.26 12.95,49.91 14.73,51.69 16.89,51.69 17.65,52.45
  Bottom 1.016: 17.65,52.45 LED_MATRIX1.29
ROW6
  Bottom 0.254: 15.37,52.7 14.99,52.7 12.45,50.16 12.45,47.88 12.95,47.37 20.95,47.37 21.46,47.88 U2.16 21.46,49.15
  Bottom 1.016: 15.37,52.7 LED_MATRIX1.30
ROW7
  Bottom 0.254: U2.17 22.73,47.5 22.1,46.86 12.7,46.86 11.94,47.62 11.94,51.82 12.57,52.45
  Bottom 1.016: 12.57,52.45 LED_MATRIX1.31
ROW8
  Bottom 0.254: U2.18 24,47.24 22.99,46.23 12.45,46.23 10.92,47.75 10.92,50.42
  Bottom 1.016: 10.92,50.42 10.92,53.37 LED_MATRIX1.32
SR_DATA  (via drill 0.6)
  Top 0.61: v21.72,26.54 24.13,24.13 37.59,24.13 v42.55,29.08
  Bottom 0.508: v21.72,26.54 20.83,25.65 IC1.14 | U1.11 42.29,28.83 v42.55,29.08
SR_LATCH/ICSPCLK  (via drill 0.6)
  Top 0.61: v42.93,37.47 42.93,30.99 v41.02,29.08 27.81,29.08 27.3,29.59
  Top 0.813: ICSP.5 27.3,30.7 27.3,29.59
  Bottom 0.508: IC3.12 41.66,26.16 41.02,26.8 U1.12 v41.02,29.08 | 19.56,31.11 20.7,32.26 26.8,32.26 27.3,31.75
  Bottom 0.61: IC1.12 18.29,26.54 19.56,27.81 IC4.12 19.56,31.11 | v42.93,37.47 IC2.12
  Bottom 0.813: ICSP.5 27.3,30.73 27.3,31.75
SR_SCK/ICSPDAT  (via drill 0.6)
  Top 0.508: v17.02,26.42 17.14,26.54 v19.94,26.54
  Top 0.61: v44.2,37.34 44.2,26.67 v40.39,22.86 v28.57,22.86 23.62,22.86 v19.94,26.54
  Bottom 0.254: IC2.11 44.2,34.92 | IC1.11 17.02,24.64
  Bottom 0.508: v40.39,22.86 IC3.11 40.39,26.04 39.75,26.67 U1.13 | v44.2,37.34 IC2.11 | IC1.11 v17.02,26.42
  Bottom 0.61: v19.94,26.54 20.83,27.43 IC4.11
  Bottom 0.813: ICSP.4 28.57,30.72 v28.57,22.86

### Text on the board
tNames: 32 | 17 | GND | GND | GND | GND | DATA | DATA | LATCH | LATCH | SCK | SCK | VCC | VCC | 5VDC Only!!! | 5VDC Only!!! | 1 | 16
bNames: MOD-LED8x8RGB Rev.B | https://www.olimex.com | 32 | <C> 2013 | 17 | GND | GND | GND | GND | DATA | DATA | LATCH | LATCH | SCK | SCK | VCC | VCC | + | + | 5VDC Only!!! | 5VDC Only!!! | 1 | 16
